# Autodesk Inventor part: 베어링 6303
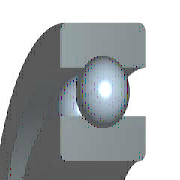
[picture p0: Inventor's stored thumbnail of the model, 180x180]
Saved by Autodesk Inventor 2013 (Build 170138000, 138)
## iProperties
IsCustomPart: 1
Created: 2012-02
Part Number: 베어링 6303
Material: 강철, 연강
Description: 단열 볼 베어링
Document SubType Name: Modeling
Standard: JIS B 1521
Designer: mdu-01
Standards Organization: JIS
Language: ko-KR
Size Designation: SKF 6303
Categories: <MemberInstance><Categories><Category DisplayName="샤프트 부품" InternalName="7f7aeb1f-a693-4053-b835-cee3144e0d98" Mnemonic="SHFT"><Category DisplayName="베어링" Inter
Density: 7.86 g/cm^3
Mass: 109.207 g
Surface Area: 91.3626 cm^2
Volume: 13.894 cm^3
Author: mdu-01
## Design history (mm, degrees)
node "WorkPoint1"
node "WorkAxis1"
node "WorkPlane3"
node "WorkPlane4"
node "WorkPoint2"
body "Solid1"
node "스케치1"
revolve "회전1" stored, may be unused: angle "d6" = 360 deg
revolve "회전2" stored, may be unused: angle "d10" = 360 deg
node "스케치4"
revolve "회전3" stored, may be unused: angle "d16" = 360 deg
pattern_circular "원형 배열1" dims "d17" = 57.33333 (= msp_pocet), angle "d19" = 360 deg
fillet "모깎기1" dims "d20" = 1 (= r)
sketch "스케치2"
  geometry: L1 (8.5, 14)-(23.5, 14); L2 (8.5, 0)-(8.5, 14); L3 (23.5, 0)-(8.5, 0); L4 (23.5, 14)-(23.5, 0); L5 (0, 0)-(0, 20); L6 (0, 0)-(0, 20); L7 (-7.2, 0)-(43.2, 0) reference
  constraints: 12 end point, 3 vertical, 2 horizontal, 1 collinear, 1 other
  dimensions: "d1" = 17 diameter of L1.start L5 (= Diam); "d3" = 47 diameter of L1.end L5 (= DD); "d5" = 14 distance of L2.start L1.start (= msp_mdtd2)
sketch "스케치3"
  geometry: L1 (18.7, 14)-(18.7, 10.6); L2 (13.3, 14)-(18.7, 14); L3 (13.3, 10.6)-(13.3, 14); L4 (13.3, 0)-(13.3, 3.4); L5 (18.7, 0)-(13.3, 0); L6 (18.7, 3.4)-(18.7, 0); L7 (23.5, 0)-(-23.5, 0) reference; L8 (23.5, 14)-(-23.5, 14) reference; L9 (0, -42.29)-(0, 61.29); L10 (0, 82.007)-(0, -63.007) reference; A1 r 4.5 centre (16, 7) between (18.7, 3.4) and (18.7, 10.6); A2 r 4.5 centre (16, 7) between (13.3, 10.6) and (13.3, 3.4)
  constraints: 14 end point, 4 collinear, 4 point on circle, 4 vertical, 2 centre point, 2 concentric, 2 horizontal, 2 point on line
  dimensions: "d9" = 9 diameter of A1 (= msp_mdtd6); "d21" = 13.3 distance between parallel lines of L9 L4 (= 0.5 x msp_d1); "d22" = 16 distance from line of L9 A1.centre (= 0.5 x msp_ds); "d23" = 18.7 distance between parallel lines of L9 L6 (= 0.5 x msp_dd1)
sketch "스케치5"
  geometry: L1 (16, 2.5)-(16, 11.5); L2 (18.7, 0)-(-18.7, 0) reference; L3 (16, 2.5)-(16, 11.5); A1 r 4.5 centre (16, 7) between (16, 2.5) and (16, 11.5); A2 r 4.5 centre (16, 7) between (18.7, 3.4) and (18.7, 10.6) reference
  constraints: 4 end point, 2 point on circle, 1 centre point, 1 concentric, 1 vertical
  dimensions: "d13" = 0 horizontal distance of A1.centre L1.start; "d15" = 9.0001 diameter of A1 (computed from msp_mdtd6)
other parameters: "Diam" = 17 [user parameter; used in 3 equation terms], "DD" = 47 [user parameter; used in 3 equation terms], "B" = 14 [user parameter; used in 1 equation term], "r" = 1 [user parameter; used in 1 equation term], "msp_ds" = 32 (= 0.5 x Diam + 0.5 x DD) [user parameter; used in 5 equation terms], "msp_d0" = 9 (= -0.3 x Diam + 0.3 x DD) [user parameter; used in 4 equation terms], "msp_d1" = 26.6 (= msp_ds - 0.6 x msp_d0) [user parameter; used in 1 equation term], "msp_dd1" = 37.4 (= msp_ds + 0.6 x msp_d0) [user parameter; used in 1 equation term], "msp_pom" = 48 (= 1.5 x msp_ds) [user parameter; used in 1 equation term], "msp_mdtd2" = 14 (= B) [user parameter; used in 3 equation terms], "msp_mdtd4" = 32 (= msp_ds) [user parameter], "msp_mdtd6" = 9 (= msp_d0) [user parameter; used in 2 equation terms], "msp_mdtd7" = 7 (= 0.5 x msp_mdtd2) [user parameter], "msp_pocet" = 57.33333 (computed from msp_d0, msp_pom) [user parameter; used in 1 equation term], "d2" = 72 (derived), "d4" = 19 (derived), "d7" = 0, "d8" = 15.6 (derived), "d11" = -14 (computed from msp_mdtd2), "d12" = 0 (derived), "d14" = 15.6001 (derived), "d26" = 0, "d27" = 0, "d28" = 0, "d29" = 0, "d30" = 0
